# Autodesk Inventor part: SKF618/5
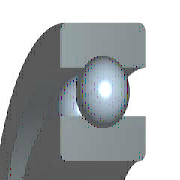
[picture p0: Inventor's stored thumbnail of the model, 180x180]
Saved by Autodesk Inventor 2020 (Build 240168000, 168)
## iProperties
Created: 2019-01
Part Number: SKF618/5
Material: Acier, doux
Description: Roulements à bille à gorge profonde, rangée unique
Document SubType Name: Modeling
Standard: SKF
Designer: bruno
Language: fr-FR
Size Designation: SKF618/5
Categories: <MemberInstance><Categories><Category DisplayName="Pièces d'arbre" InternalName="7f7aeb1f-a693-4053-b835-cee3144e0d98" Mnemonic="SHFT"><Category DisplayName="Ro
Density: 7.85 g/cm^3
Appearance: Semi-poli
IsCustomPart: 0
Author: bruno
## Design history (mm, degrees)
node "WorkPoint1"
node "WorkAxis1"
node "WorkPlane3"
node "WorkPlane4"
node "WorkPoint2"
pattern_circular "RéseauPolaire1" dims "d17" = 70.66667 (= msp_pocet), angle "d19" = 360 deg
body "Solid1"
node "Esquisse1"
revolve "Révolution1" stored, may be unused: angle "d6" = 360 deg
revolve "Révolution2" stored, may be unused: angle "d10" = 360 deg
node "Esquisse4"
revolve "Révolution3" stored, may be unused: angle "d16" = 360 deg
fillet "Congé1" dims "d20" = 0.15 (= r)
sketch "Esquisse2"
  geometry: L1 (2.5, 3)-(5.5, 3); L2 (2.5, 0)-(2.5, 3); L3 (5.5, 0)-(2.5, 0); L4 (5.5, 3)-(5.5, 0); L5 (0, 0)-(0, 20); L6 (0, 0)-(0, 20); L7 (-7.2, 0)-(43.2, 0) reference
  constraints: 12 end point, 3 vertical, 2 horizontal, 1 collinear, 1 other
  dimensions: "d1" = 5 diameter of L1.start L5 (= Diam); "d3" = 11 diameter of L1.end L5 (= DD); "d5" = 3 distance of L2.start L1.start (= msp_mdtd2)
sketch "Esquisse3"
  geometry: L1 (4.54, 3)-(4.54, 2.22); L2 (3.46, 3)-(4.54, 3); L3 (3.46, 2.22)-(3.46, 3); L4 (3.46, 0)-(3.46, 0.78); L5 (4.54, 0)-(3.46, 0); L6 (4.54, 0.78)-(4.54, 0); L7 (5.5, 0)-(-5.5, 0) reference; L8 (5.5, 3)-(-5.5, 3) reference; L9 (0, -42.29)-(0, 61.29); L10 (0, 82.007)-(0, -63.007) reference; A1 r 0.9 centre (4, 1.5) between (4.54, 0.78) and (4.54, 2.22); A2 r 0.9 centre (4, 1.5) between (3.46, 2.22) and (3.46, 0.78)
  constraints: 14 end point, 4 collinear, 4 point on circle, 4 vertical, 2 centre point, 2 concentric, 2 horizontal, 2 point on line
  dimensions: "d9" = 1.8 diameter of A1 (= msp_mdtd6); "d21" = 3.46 distance between parallel lines of L9 L4 (= 0.5 x msp_d1); "d22" = 4 distance from line of L9 A1.centre (= 0.5 x msp_ds); "d23" = 4.54 distance between parallel lines of L9 L6 (= 0.5 x msp_dd1)
sketch "Esquisse5"
  geometry: L1 (4, 0.6)-(4, 2.4); L2 (4.54, 0)-(-4.54, 0) reference; L3 (4, 0.6)-(4, 2.4); A1 r 0.9 centre (4, 1.5) between (4, 0.6) and (4, 2.4); A2 r 0.9 centre (4, 1.5) between (4.54, 0.78) and (4.54, 2.22) reference
  constraints: 4 end point, 2 point on circle, 1 centre point, 1 concentric, 1 vertical
  dimensions: "d13" = 0 horizontal distance of A1.centre L1.start; "d15" = 1.8001 diameter of A1 (computed from msp_mdtd6)
other parameters: "Diam" = 5 [user parameter; used in 3 equation terms], "DD" = 11 [user parameter; used in 3 equation terms], "B" = 3 [user parameter; used in 1 equation term], "r" = 0.15 [user parameter; used in 1 equation term], "msp_ds" = 8 (= 0.5 x Diam + 0.5 x DD) [user parameter; used in 5 equation terms], "msp_d0" = 1.8 (= -0.3 x Diam + 0.3 x DD) [user parameter; used in 4 equation terms], "msp_d1" = 6.92 (= msp_ds - 0.6 x msp_d0) [user parameter; used in 1 equation term], "msp_dd1" = 9.08 (= msp_ds + 0.6 x msp_d0) [user parameter; used in 1 equation term], "msp_pom" = 12 (= 1.5 x msp_ds) [user parameter; used in 1 equation term], "msp_mdtd2" = 3 (= B) [user parameter; used in 3 equation terms], "msp_mdtd4" = 8 (= msp_ds) [user parameter], "msp_mdtd6" = 1.8 (= msp_d0) [user parameter; used in 2 equation terms], "msp_mdtd7" = 1.5 (= 0.5 x msp_mdtd2) [user parameter], "msp_pocet" = 70.66667 (computed from msp_d0, msp_pom) [user parameter; used in 1 equation term], "d2" = 72 (derived), "d4" = 19 (derived), "d7" = 0, "d8" = 15.6 (derived), "d11" = -3 (computed from msp_mdtd2), "d12" = 0 (derived), "d14" = 15.6001 (derived), "d26" = 0, "d27" = 0, "d28" = 0, "d29" = 0, "d30" = 0
